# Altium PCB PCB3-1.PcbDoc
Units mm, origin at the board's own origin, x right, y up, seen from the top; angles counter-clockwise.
Board outline 20 x 20 mm, 2 copper layers (Top Layer, Bottom Layer); 6 components, 14 nets, 39 pads, 0 vias.
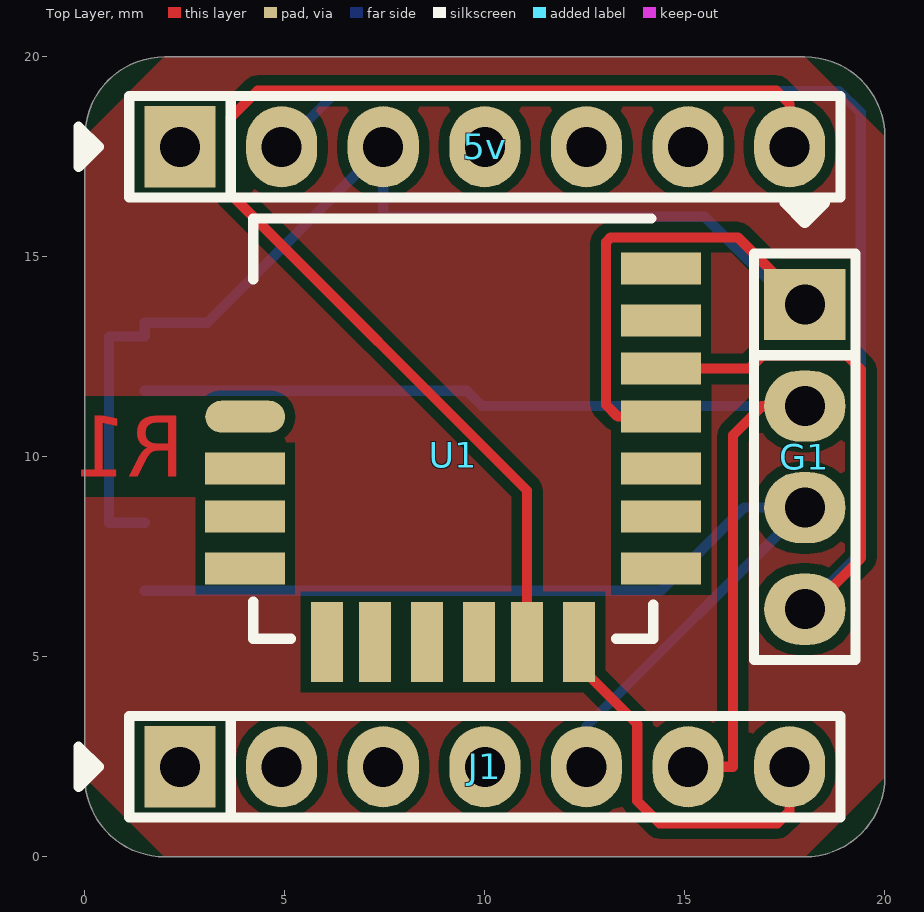
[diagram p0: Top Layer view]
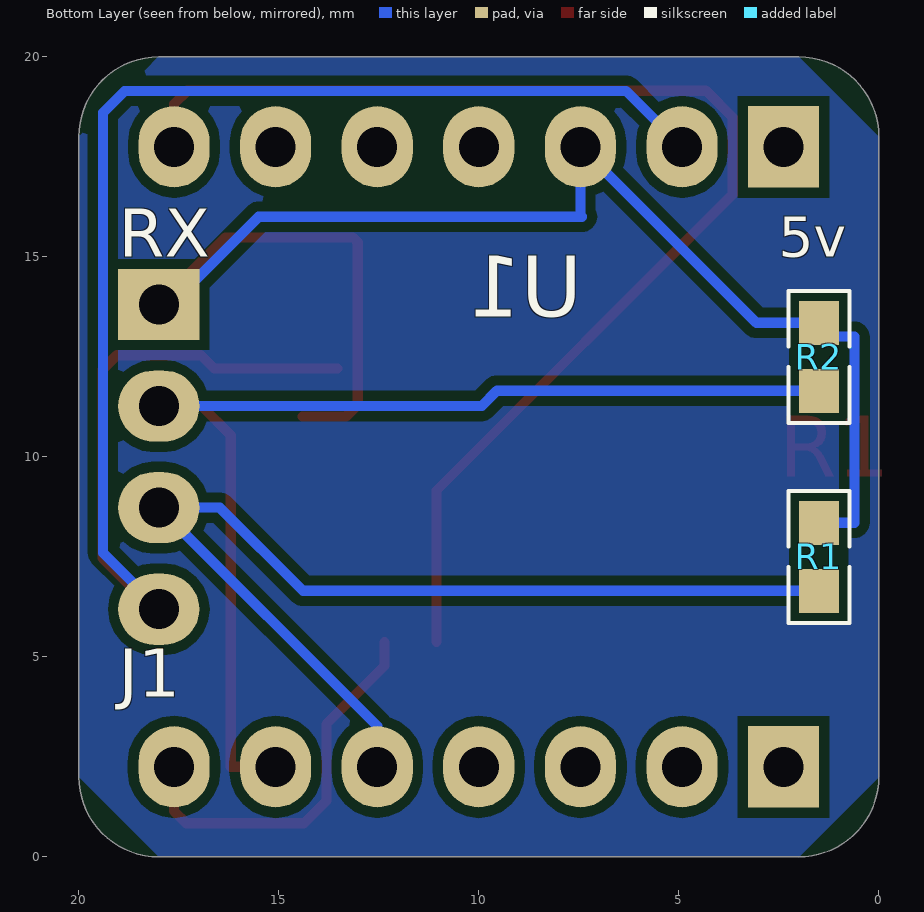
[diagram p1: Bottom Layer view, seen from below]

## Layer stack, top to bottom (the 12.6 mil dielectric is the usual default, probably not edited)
Top Solder: solder mask 0.0102, Solder Resist, Dk 3.5
Top Layer: signal copper 0.0356
Dielectric 1: dielectric 0.32, FR-4, Dk 4.8
Bottom Layer: signal copper 0.0356
Bottom Solder: solder mask 0.0102, Solder Resist, Dk 3.5

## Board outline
0,2 0,18 cw(c2,18) 2,20 18,20 cw(c18,18) 20,18 20,2 cw(c18,2) 18,0 2,0 cw(c2,2)

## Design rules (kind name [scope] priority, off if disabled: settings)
Clearance [All] p1: gap=0.254
PolygonConnect [All] p1: connectstyle=Relief reliefconductorwidth=0.254 reliefentries=4 polygonreliefangle="90 Angle" airgapwidth=0.254
RoutingVias [All] p1: holewidth=0.711 width=1.27 viastyle="Through Hole" minholewidth=0.711 minwidth=1.27 maxholewidth=0.711 maxwidth=1.27
SolderMaskExpansion [All] p1: expansion=0.102
Width [All] p1: maxlimit=0.254 minlimit=0.254 preferedwidth=0.254
29 further rules are at their usual default settings.

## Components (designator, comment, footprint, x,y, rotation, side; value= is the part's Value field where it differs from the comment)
5v "HDR1x7" PIN-7-2.54-1.0 10,17.75 r0 top (schematic designator J2)
G1 "HDR1x4" PIN-4-2.54-1.0 18,10 r270 top
J1 "HDR1x7" PIN-7-2.54-1.0 10,2.25 r0 top
R1 "Res1" 0603-1 1.5,7.5 r90 bottom
R2 "Res1" 0603-1 1.5,12.5 r90 bottom
U1 "WH-BLE103" PCBComponent_1 356,850 r0 top

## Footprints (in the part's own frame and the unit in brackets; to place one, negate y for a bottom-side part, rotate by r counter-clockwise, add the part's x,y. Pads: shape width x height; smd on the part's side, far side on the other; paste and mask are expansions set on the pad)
0603-1 [mm] "贴片带丝印"
  rect 1.1x1 smd: 1(-0.85,0) 2(0.85,0)
  silkscreen extent -1.65,-0.76 1.65,0.76, body extent -1.14,-0.38 1.14,0.38, height 1
PCBComponent_1 [mm]
  oval 2x0.8 smd: 1(-351.99,-838.996)
  rect 2x0.8 smd: 2(-351.99,-840.296) 3(-351.99,-841.496) 4(-351.99,-842.796) 11(-341.59,-842.796) 12(-341.59,-841.496) 13(-341.59,-840.296) 14(-341.59,-838.996) 15(-341.59,-837.796) 16(-341.59,-836.596) 17(-341.59,-835.296)
  rect 0.8x2 smd: 5(-349.944,-844.632) 6(-348.744,-844.632) 7(-347.444,-844.632) 8(-346.144,-844.632) 9(-344.944,-844.632) 10(-343.644,-844.632)
  silkscreen extent -351.79,-844.55 -341.79,-834.04
PIN-4-2.54-1.0 [mil] "Pin Header"
  rect 70x80 hole 39.37: 1(-150,0)
  oval 70x80 hole 39.37: 2(-50,0) 3(50,0) 4(150,0)
  silkscreen extent -250,-50 200,50, body extent -200,-50 200,50, height 398
PIN-7-2.54-1.0 [mil] "Pin Header"
  rect 70x80 hole 39.37: 1(-300,0)
  oval 70x80 hole 39.37: 2(-200,0) 3(-100,0) 4(0,0) 5(100,0) 6(200,0) 7(300,0)
  silkscreen extent -400,-50 350,50, body extent -350,-50 350,50, height 398

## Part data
5v G1 J1: "Connector"
R1 R2: "贴片电阻"

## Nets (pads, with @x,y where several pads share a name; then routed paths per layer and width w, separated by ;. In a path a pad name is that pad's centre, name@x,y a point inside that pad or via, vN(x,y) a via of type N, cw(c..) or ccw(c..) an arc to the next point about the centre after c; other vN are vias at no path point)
3.3V: 5v.3 G1.1 R1.2 R2.2 U1.14 | length 39.1
  Top Layer w0.254: U1.14 13.326,11.004 13.028,11.302 13.028,15.366 13.147,15.485 16.325,15.485 G1.1
  Bottom Layer w0.254: R1.2 0.608,8.35 0.608,13.004 1.5,13.004 R2.2 3.06,13.35 5v.3 7.46,16.04 7.42,16 15.5,16 17.69,13.81 G1.1
5V: 5v.1
D0: J1.1
D1: J1.2
D2: J1.3
D3: J1.4
D8: 5v.6
D9: 5v.5
D10: 5v.4
GND: 5v.2 G1.4 U1.15 | length 41.1
  Top Layer w0.254: U1.15@13.536,12.204 U1.15 16.61,12.204 16.946,12.54 19.048,12.54 19.404,12.184 19.404,7.467 18.127,6.19 G1.4
  Bottom Layer w0.254: 5v.2 6.317,19.147 18.853,19.147 19.397,18.603 19.397,7.603 18,6.206 G1.4
RX: 5v.7 U1.9 | length 31.6
  Top Layer w0.254: U1.9 11.056,9.16 3.65,16.565 3.65,18.485 4.316,19.151 17.29,19.151 17.62,18.82 5v.7
SCL: G1.2 J1.6 R2.1 | length 28.2
  Top Layer w0.254: J1.6 16.203,2.25 16.203,10.54 16.933,11.27 G1.2
  Bottom Layer w0.254: R2.1 9.548,11.65 9.928,11.27 G1.2
SDA: G1.3 J1.5 R1.1 | length 26.1
  Bottom Layer w0.254: R1.1 14.396,6.65 16.476,8.73 G1.3 12.54,3.27 J1.5
TX: J1.7 U1.10 | length 9.8
  Top Layer w0.254: U1.10 12.356,4.774 13.81,3.32 13.81,1.396 14.369,0.837 17.315,0.837 17.62,1.142 J1.7
pads on no net: U1.1 U1.2 U1.3 U1.4 U1.5 U1.6 U1.7 U1.8 U1.11 U1.12 U1.13 U1.16 U1.17

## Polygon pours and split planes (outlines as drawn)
no net on Top Layer "Top Layer-No Net" (solid, pour order 4): -0.01,18 2,20.01 17.99,20.01 18,20 20,18 20,2.01 20.01,2 18.01,0 18,0 2.01,0 2,-0.01 -0.01,2 -0.01,17.99 0,18
no net on Bottom Layer "Top Layer-No Net" (solid, pour order 6): 0,18 2,20 17.99,20 18,20.01 20.01,18 20.01,2.01 20,2 18,0 2.01,0 2,-0.01 -0.01,2 -0.01,18

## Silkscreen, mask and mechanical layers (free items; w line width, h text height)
Bottom Overlay:
  text "RX" at 19,15 h1.2
Mechanical 1:
  lines w0.254: 0,2 ccw(c2,2) 2,0 18,0 ccw(c18,2) 20,2 20,18 ccw(c18,18) 18,20 14,20 2,20 ccw(c2,18) 0,18 0,2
